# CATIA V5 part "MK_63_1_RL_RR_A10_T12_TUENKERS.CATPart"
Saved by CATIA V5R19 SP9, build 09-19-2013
Part number: MK_63_1_RL_RR_A10_T12_TUENKERS
Material "MISCHDICHTE": density 5043 kg/m3, Young's modulus 2e+11 Pa, Poisson ratio 0.266
Bounding box of the stored display mesh (mm): x -193.5 to 132.266, y -121.5 to 144, z -122.161 to 122.161
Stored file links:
  G:\Konstruktion\Modelle\Catia_V5\MK_63_1_RL_RR_A10_T12_TUENKERS.CATPart
  G:\Konstruktion\Modelle\Catia_V5\Spannarme\SPANNARM_KPL_63_A10_217498_TUENKERS.CATPart
  C:\Catia\Tuenkers_B19SP9HF86_64\win_b64\reffiles\standard\MetricThickPitch.txt
  G:\Konstruktion\Modelle\Catia_V5\MK_63_1_A10_T00_TUENKERS.CATPart
  G:\Konstruktion\Modelle\Catia_V5\MK2_63_1_A40_T12_TUENKERS.CATPart
  G:\Konstruktion\Modelle\Catia_V5\V2_63_1_BR3_ZL_ZR_RL_RR_A40_T12_TUENKERS.CATPart
  HANDHEBEL_KPL_50_63_TUENKERS.CATPart
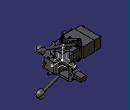
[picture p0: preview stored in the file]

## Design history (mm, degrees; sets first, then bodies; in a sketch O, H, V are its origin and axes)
AxisSystem1: origin (0, 0, 0), X (1, 0, 0), Y (0, 1, 0), Z (0, 0, 1)
Body1 (main body)
  Body2 "*DIT1\\*DIT2\\"
    Solid1: solid without history
  Assemble1: tool Body2
  Body3 "*DIT1\\*DIT3"
    Solid2 "Solid.1": solid without history
  Assemble2: tool Body3
  Body4 "*DIT1\\*DIT12\\*DIT16\\"
    Solid3 "Solid.1": solid without history
  Assemble3: tool Body4
  Body5 "*DIT1\\*DIT12\\*DIT17\\"
    Solid4 "Solid.1": solid without history
  Assemble4: tool Body5
  Body6 "*DIT1\\*DIT12\\MK_MK2_63_1_A10_A11_A12_T12_081112_3D_xSET4_2.1"
    Solid5 "Solid.1": solid without history
    Body7 "*DIT1\\*DIT12\\MK_MK2_63_1_A10_A11_A12_T12_081112_3D_xSET4_2.1\\Body.11 ( *SOL16 - wsp GEHAEUSE -  )"
      Solid6 "Solid.1": solid without history
    Add1 "*DIT1\\*DIT12\\MK_MK2_63_1_A10_A11_A12_T12_081112_3D_xSET4_2.1\\Body.11 ( *SOL16 - wsp GEHAEUSE -  )": tool Body7
    Body8 "*DIT1\\*DIT12\\MK_MK2_63_1_A10_A11_A12_T12_081112_3D_xSET4_2.1\\Body.12 ( *SOL17 - wsp GEHAEUSE -  )"
      Solid7 "Solid.1": solid without history
    Add2 "*DIT1\\*DIT12\\MK_MK2_63_1_A10_A11_A12_T12_081112_3D_xSET4_2.1\\Body.12 ( *SOL17 - wsp GEHAEUSE -  )": tool Body8
    Body9 "*DIT1\\*DIT12\\MK_MK2_63_1_A10_A11_A12_T12_081112_3D_xSET4_2.1\\Body.14 ( *SOL18 - wsp GEHAEUSE -  )"
      Solid8 "Solid.1": solid without history
    Add3 "*DIT1\\*DIT12\\MK_MK2_63_1_A10_A11_A12_T12_081112_3D_xSET4_2.1\\Body.14 ( *SOL18 - wsp GEHAEUSE -  )": tool Body9
  Assemble5: tool Body6
  Body10 "*DIT1\\MK_MK2_63_1_A10_A11_A12_T12_081112_3D_xSET2_1.1"
    Solid9 "Solid.1": solid without history
  Assemble6: tool Body10
  Rotate1: Axis edge [XY plane of AxisSystem1 | ZX plane of AxisSystem1], Angle 90, ToTransfor Assemble6
  Body11
    Body12 "*DIT1\\MK_MK2_63_1_A10_A11_A12_T12_081112_3D_xSET2_1.1\\Body.2 ( *SOL2 - wsp MK_MK2 63_1 -  )"
      Solid10 "Solid.1": solid without history
    Assemble7: tool Body12
    Body13 "*DIT1\\MK_MK2_63_1_A10_A11_A12_T12_081112_3D_xSET2_1.1\\Body.3 ( *SOL3 - wsp MK_MK2 63_1 -  )"
      Solid11 "Solid.1": solid without history
    Assemble8: tool Body13
    Body14 "*DIT1\\MK_MK2_63_1_A10_A11_A12_T12_081112_3D_xSET2_1.1\\Body.4 ( *SOL4 - wsp MK_MK2 63_1 -  )"
      Solid12 "Solid.1": solid without history
    Assemble9: tool Body14
    Body15 "*DIT1\\MK_MK2_63_1_A10_A11_A12_T12_081112_3D_xSET2_1.1\\Body.5 ( *SOL5 - wsp MK_MK2 63_1 -  )"
      Solid13 "Solid.1": solid without history
    Assemble10: tool Body15
    Body16 "*DIT1\\MK_MK2_63_1_A10_A11_A12_T12_081112_3D_xSET2_1.1\\Body.6 ( *SOL6 - wsp MK_MK2 63_1 -  )"
      Solid14 "Solid.1": solid without history
    Assemble11: tool Body16
    Rotate2: Axis edge, Angle 90, ToTransfor Assemble11
    Translate1: Direction edge [YZ plane of AxisSystem1 | XY plane of AxisSystem1], Length -1, ToTransfor Rotate2
  Assemble12: tool Body11
Body17 "Spannarm_kpl_63_A10_217498_Tuenkers", material "Steel"
  Sketch1 on xy-plane, origin (0, 0, 0), H (1, 0, 0), V (0, 1, 0)
    line L1 (43, 144) -> (15, 144)
    arc A1 centre (21.5, 11.6005) radius 20 from (35.6421, -2.5416) to (41.5, 11.6005) ccw
    line L2 (35.6421, -2.5416) -> (19.0919, -19.0919)
    line L3 (10.9602, 10.9602) -> (10.9602, -10.9602)
    line L4 (10.9602, 10.9602) -> (-10.9602, 10.9602)
    line L5 (-19.0919, 19.0919) -> (-10.9602, 10.9602)
    line L6 (10.6421, 48.8259) -> (-19.0919, 19.0919)
    line L7 (16.5, 62.968) -> (16.5, 78.0635)
    line L8 (43, 144) -> (43, 80)
    line L9 (10.9602, -10.9602) -> (19.0919, -19.0919)
    point P7 (10.9602, 10.9602)
    point P10 (-1.4396, 36.7442)
    point P11 (73, 37.6447)
    point P12 (45, 51.7188)
    reference intersected line E1 through (0, 0) direction (-0.7071, 0.7071)
    reference intersected line E2 through (0, 0) direction (-0.7071, 0.7071)
    reference intersected line E3 through (0, 0) direction (-0.7071, 0.7071)
    reference intersected line E4 through (0, 0) direction (0, 1) from yz-plane
    reference intersected line E5 through (0, 0) direction (-1, 0) from zx-plane
    line L10 (41.5, 78.0635) -> (41.5, 11.6005)
    line L11 (15, 80) -> (15, 144)
    arc A2 centre (-3.5, 62.968) radius 20 from (10.6421, 48.8259) to (16.5, 62.968) ccw
    arc A3 centre (14.5, 78.0635) radius 2 from (16.5, 78.0635) to (15, 80) ccw
    arc A4 centre (43.5, 78.0635) radius 2 from (41.5, 78.0635) to (43, 80) cw
    reference intersected line E6 through (0, 0) direction (0, 1) from yz-plane
    radius A1 = 20
    angle L4 L5 = 45
    distance P7 L2 = 27
    distance L2 L6 = 54
    angle L2 L9 = 90
    distance P7 E1 = 15.5
    distance E4 L3 = 10.9602
    distance E5 L1 = 144
    distance P10 L1 = 107.2558
    radius A4 = 2
    radius A3 = 2
    distance L10 L8 = 1.5
    distance L7 L10 = 25
    distance E6 L11 = 15
    distance L11 L7 = 1.5
    length L8 = 64
    radius A2 = 20
    length L11 = 64
    tangency: A1 L2, A1 L10, A4 L10, A2 L7, L6 A2, A3 L7
    coincidence: L9 E2, L5 E3, L6 P10
  Pad1: profile Sketch1, direction (0, 0, 1), length 39, opposite side length 39
  Chamfer1: length 0.1, angle 45, on edge [face of Pad1 from Sketch1.L3 | end face of Pad1]; edge [face of Pad1 from Sketch1.L4 | end face of Pad1]; edge [start face of Pad1 | face of Pad1 from Sketch1.L4]; edge [start face of Pad1 | face of Pad1 from Sketch1.L3]
  Sketch2 on face of Pad1 from Sketch1.L8, origin (43, 0, 0), H (0, 1, 0), V (0, 0, 1)
    line L1 (144, -10) -> (144, 10)
    line L2 (103, 10) -> (144, 10)
    arc A1 centre (103, 18) radius 8 from (103, 10) to (95, 18) cw
    line L3 (95, 24.9808) -> (95, 18)
    line L4 (-20, 39) -> (70, 39)
    line L5 (-20, 39) -> (-20, 28)
    line L6 (74, 28) -> (-20, 28)
    arc A2 centre (74, 22) radius 6 from (74, 28) to (80, 22) cw
    line L7 (80, 22) -> (80, -22)
    arc A3 centre (74, -22) radius 6 from (80, -22) to (74, -28) cw
    line L8 (-20, -28) -> (74, -28)
    line L9 (-20, -28) -> (-20, -39)
    line L10 (-20, -39) -> (70, -39)
    line L11 (95, -24.9808) -> (95, -18)
    arc A4 centre (103, -18) radius 8 from (95, -18) to (103, -10) cw
    line L12 (103, -10) -> (144, -10)
    reference intersected line E1 through (0, 0) direction (-1, 0) from xy-plane
    reference intersected line E2 through (0, 0) direction (0, 1) from zx-plane
    reference intersected line E3 through (0, 0) direction (0, 1) from zx-plane
    reference intersected line E4 through (0, 0) direction (0, 1) from zx-plane
    line L13 (-30, -44) -> (160, -44)
    line L14 (160, -44) -> (160, 44)
    line L15 (160, 44) -> (-30, 44)
    line L16 (-30, 44) -> (-30, -44)
    reference intersected line E5 through (0, 0) direction (-1, 0) from xy-plane
    reference intersected line E6 through (0, 0) direction (0, 1) from zx-plane
    line L17 (72.5882, -38.6593) -> (87.5882, -34.64)
    line L18 (87.5882, 34.64) -> (72.5882, 38.6593)
    arc A5 centre (85, 24.9808) radius 10 from (95, 24.9808) to (87.5882, 34.64) ccw
    arc A6 centre (70, 29) radius 10 from (72.5882, 38.6593) to (70, 39) ccw
    point P23 (70, 39)
    arc A7 centre (70, -29) radius 10 from (72.5882, -38.6593) to (70, -39) cw
    point P26 (70, -39)
    arc A8 centre (85, -24.9808) radius 10 from (95, -24.9808) to (87.5882, -34.64) cw
    distance L12 E1 = 10
    distance L12 L2 = 20
    distance L4 L10 = 78
    distance L6 L8 = 56
    distance L10 L12 = 29
    distance L8 L10 = 11
    radius A2 = 6
    radius A3 = 6
    radius A1 = 8
    radius A4 = 8
    distance L7 E2 = 80
    distance L3 E3 = 95
    distance L1 L5 = 164
    distance E4 L1 = 144
    distance L16 L14 = 190
    distance L15 L13 = 88
    distance L13 E5 = 44
    distance L14 E6 = 160
    angle L18 L4 = 15
    distance P23 L3 = 25
    radius A6 = 10
    radius A5 = 10
    angle L10 L17 = 15
    distance L11 P26 = 25
    radius A7 = 10
    radius A8 = 10
    tangency: L6 A2, A2 L7, L7 A3, A3 L8, L3 A1, A1 L2, A4 L12, A4 L11, A5 L3, A5 L18, A6 L18, A6 L4, A7 L17, A7 L10, A8 L11, A8 L17
    vertical: L1 V, L14 V, L16 V
    horizontal: L12 H, L13 H, L15 H
    coincidence: L5 L9, L11 L3
  Pocket1: profile Sketch2, direction (-1, 0, 0), length 95
  Sketch3 on face of Pad1 from Sketch1.L8, origin (43, 131.0889, -0.3784), H (0, 1, 0), V (0, 0, 1)
    point P1 (3.9111, 0.3784)
    reference intersected line E1 through (0, 0.3784) direction (-1, 0) from xy-plane
    reference intersected line E2 through (-131.0889, 0) direction (0, 1) from zx-plane
    reference intersected line E3 through (-131.0889, 0) direction (0, 1) from zx-plane
    reference intersected line E4 (12.9111, -38.6216) -> (-51.0889, -38.6216) from start face of Pad1
    distance P1 E2 = 135
    distance E3 E4 = 0
    coincidence: P1 E1
  Hole1: placed by Sketch3, at (43, 135, 0) direction (-1, 0, 0), diameter 6, through (limit type 6)
  Sketch4 on face of Pad1 from Sketch1.L8, origin (43, 113.9529, 0.5693), H (0, 1, 0), V (0, 0, 1)
    point P1 (-8.9529, -0.5693)
    reference projected point E1 (21.0471, -0.5693) from axis of face of Hole1
    reference intersected line E2 through (0, -0.5693) direction (-1, 0) from xy-plane
    distance P1 E1 = 30
    coincidence: P1 E2
  Hole2: placed by Sketch4, at (43, 105, 0) direction (-1, 0, 0), diameter 6, through (limit type 6)
  Sketch5 on face of Pad1 from Sketch1.L8, origin (43, 123.4122, -0.1089), H (0, 1, 0), V (0, 0, 1)
    point P1 (-3.4122, 0.1089)
    reference projected point E1 (11.5878, 0.1089) from axis of face of Hole1
    reference projected point E2 (-18.4122, 0.1089) from axis of face of Hole2
    distance P1 E1 = 15
    distance E2 P1 = 15
  Hole3: placed by Sketch5, at (43, 120, 0) direction (-1, 0, 0), diameter 9, through (limit type 6)
  Sketch6 on face of Pad1 from Sketch1.L8, origin (43, 93.5248, 1.4062), H (0, 1, 0), V (0, 0, 1)
    point P1 (-3.5248, -1.4062)
    reference projected point E1 (26.4752, -1.4062) from axis of face of Hole3
    reference projected point E2 (11.4752, -1.4062) from axis of face of Hole2
    distance P1 E1 = 30
    distance P1 E2 = 15
  Hole4: placed by Sketch6, at (43, 90, 0) direction (-1, 0, 0), diameter 9, through (limit type 6)
  Sketch7 on face of Pad1 from Sketch1.L9, origin (13.7879, -13.7879, 28.7565), H (0.7071, -0.7071, 0), V (0, 0, 1)
    point P1 (0.5009, 4.2435)
    reference intersected line E1 through (0, -28.7565) direction (-1, 0) from xy-plane
    reference projected line E2 (-19.4991, -67.7565) -> (-19.4991, 10.2435) from edge [face of Pad1 from Sketch1.L3 | face of Pad1 from Sketch1.L4]
    distance P1 E1 = 33
    distance E2 P1 = 20
  Hole5: placed by Sketch7, at (14.1421, -14.1421, 33) direction (0.7071, 0.7071, 0), diameter 6.647, depth 18, V-bottom angle 120, threaded "M8", thread diameter 8, thread depth 15, pitch 1.25
  RectPattern1: of Hole5, direction 1 instances 2, spacing 66, along edge [face of Pad1 from Sketch1.L3 | face of Pad1 from Sketch1.L4] reversed, direction 2 instances 2, spacing 40, along edge [face of Pad1 from Sketch1.L9 | face of Pocket1] reversed
  Sketch8 on face of Pocket1 from Sketch2.L6, origin (0, 0, 28), H (1, 0, 0), V (0, -1, 0)
    line L1 (19.0919, 19.0919) -> (35.6421, 2.5416)
    line L2 (36.7245, 1.3692) -> (-1.4142, -36.7696)
    line L3 (-1.4142, -36.7696) -> (-19.0919, -19.0919)
    line L4 (-19.0919, -19.0919) -> (-10.96, -10.96)
    line L5 (-10.96, -10.96) -> (10.96, -10.96)
    point P5 (10.96, -10.96)
    line L6 (10.96, -10.96) -> (10.96, 10.96)
    line L7 (10.96, 10.96) -> (19.0919, 19.0919)
    reference intersected line E1 through (0, 0) direction (0.7071, -0.7071)
    reference intersected line E2 through (0, 0) direction (0.7071, 0.7071)
    reference intersected line E3 through (0, 0) direction (0.7071, -0.7071)
    arc A1 centre (21.5, -11.6005) radius 20 from (35.6421, 2.5416) to (36.7245, 1.3692) cw
    reference intersected line E4 through (0, 0) direction (0, 1) from yz-plane
    distance E1 L1 = 27
    distance L3 L1 = 54
    distance L7 L2 = 25
    angle L6 L5 = 90
    radius A1 = 20
    length L2 = 53.9363
    distance E4 L6 = 10.96
    coincidence: E2 L7, L4 L7, P5 E3
    tangency: A1 L1
  Pad2: profile Sketch8, direction (0, 0, -1), length 1
  Mirror1: of Pad2, Sketch8, about xy-plane
  Body18 "KLEMMFLANSCH KPL"
    Sketch9 on xy-plane, origin (0, 0, 0), H (1, 0, 0), V (0, 1, 0)
      line L1 (-20.5061, 17.6777) -> (-31.1375, 7.0463)
      line L2 (-31.1375, 7.0463) -> (-19.1167, -4.9745)
      line L3 (-19.1167, -4.9745) -> (-25.4806, -11.3385)
      line L4 (-25.4806, -11.3385) -> (-11.3385, -25.4806)
      line L5 (-11.3385, -25.4806) -> (-4.9745, -19.1167)
      line L6 (-4.9745, -19.1167) -> (7.0463, -31.1375)
      line L7 (7.0463, -31.1375) -> (19.0671, -19.1167)
      line L8 (19.0671, -19.1167) -> (10.9106, -10.9602)
      line L9 (10.9106, -10.9602) -> (-10.9602, -10.9602)
      point P10 (-10.9602, -10.9602)
      line L10 (-10.9602, -10.9602) -> (-10.9602, 8.1317)
      line L11 (-10.9602, 8.1317) -> (-20.5061, 17.6777)
      reference intersected line E1 through (0, 0) direction (-0.7071, 0.7071)
      reference intersected line E2 through (0, 0) direction (-0.7071, 0.7071)
      reference intersected line E3 through (0, 0) direction (-0.7071, -0.7071)
      distance L4 L8 = 26
      distance L7 L5 = 17
      distance L5 L3 = 20
      distance L7 L1 = 54
      distance L4 L6 = 9
      distance E1 P10 = 15.5
      distance L11 E2 = 2
      distance L11 L8 = 1.965
      angle L11 L10 = 135
      angle L9 L8 = 45
      distance L7 P10 = 27
      distance E3 L7 = 27
      coincidence: L2 L6
    Pad3: profile Sketch9, direction (0, 0, 1), length 39, opposite side length -27
    Chamfer2: length 0.1, angle 45, on edge [face of Pad3 from Sketch9.L9 | end face of Pad3]; edge [face of Pad3 from Sketch9.L10 | end face of Pad3]
    Sketch10 on face of Pad3 from Sketch9.L6, origin (-12.0456, -12.0456, 0), H (0.7071, -0.7071, 0), V (0, 0, 1)
      circle A1 centre (20, 33) radius 4
      point P1 (20, 33)
      circle A2 centre (-20, 33) radius 4
      point P2 (-20, 33)
      reference projected line E1 (-27, 27) -> (-10, 27) from edge [start face of Pad3 | face of Pad3 from Sketch9.L2]
      reference projected line E2 (10, 27) -> (27, 27) from edge [start face of Pad3 | face of Pad3 from Sketch9.L6]
      reference projected line E3 (27, 27) -> (27, 39) from edge [face of Pad3 from Sketch9.L7 | face of Pad3 from Sketch9.L6]
      reference projected line E4 (-27, 27) -> (-27, 39) from edge [face of Pad3 from Sketch9.L2 | face of Pad3 from Sketch9.L1]
      radius A1 = 4
      radius A2 = 4
      distance E1 P2 = 6
      distance P1 E2 = 6
      distance E3 P1 = 7
      distance P2 E4 = 7
    Pad4: profile Sketch10, direction (0.7071, 0.7071, 0), length 20
    Sketch11 on face of Pad4, origin (-12.0456, -12.0456, 0), H (0.7071, -0.7071, 0), V (0, 0, 1)
      circle A1 centre (20, 33) radius 6.5
      point P1 (20, 33)
      circle A2 centre (-20, 33) radius 6.5
      point P2 (-20, 33)
      reference projected line E1 (-27, 27) -> (-27, 39) from edge [face of Pad3 from Sketch9.L2 | face of Pad3 from Sketch9.L1]
      reference projected line E2 (27, 27) -> (27, 39) from edge [face of Pad3 from Sketch9.L7 | face of Pad3 from Sketch9.L6]
      reference projected line E3 (-27, 27) -> (-10, 27) from edge [start face of Pad3 | face of Pad3 from Sketch9.L2]
      reference projected line E4 (10, 27) -> (27, 27) from edge [start face of Pad3 | face of Pad3 from Sketch9.L6]
      radius A1 = 6.5
      radius A2 = 6.5
      distance E1 P2 = 7
      distance E2 P1 = 7
      distance E3 P2 = 6
      distance E4 P1 = 6
    Pad5: profile Sketch11, direction (-0.7071, -0.7071, 0), length 1.4
    Chamfer3: length 0.1, angle 45, on edge [face of Pad5 from Sketch11.A1 | end face of Pad5]; edge [face of Pad5 from Sketch11.A2 | end face of Pad5]
    Sketch12 on end face of Pad5, origin (-13.0355, -13.0355, 0), H (0.7071, -0.7071, 0), V (0, 0, 1)
      circle A1 centre (20, 33) radius 6.5
      point P1 (20, 33)
      circle A2 centre (-20, 33) radius 6.5
      point P2 (-20, 33)
      reference projected line E1 (10, 27) -> (27, 27) from edge [start face of Pad3 | face of Pad4]
      reference projected line E2 (27, 27) -> (27, 39) from edge [face of Pad3 from Sketch9.L7 | face of Pad3 from Sketch9.L6]
      reference projected line E3 (-27, 27) -> (-27, 39) from edge [face of Pad3 from Sketch9.L2 | face of Pad3 from Sketch9.L1]
      reference projected line E4 (-27, 27) -> (-10, 27) from edge [start face of Pad3 | face of Pad4]
      radius A1 = 6.5
      radius A2 = 6.5
      distance E1 P1 = 6
      distance E2 P1 = 7
      distance E3 P2 = 7
      distance E4 P2 = 6
    Pad6: profile Sketch12, direction (-0.7071, -0.7071, 0), length 8
    Fillet1: radius 0.5, on end face of Pad6; edge [face of Pad6 from Sketch12.A1 | end face of Pad6]
    Mirror2: of the body so far, about xy-plane, deactivated
  Assemble13: tool Body18
Body19 "ENDLAGENRASTE_LINKS"
  Solid15 "Manifold Solid #1213": solid without history
  Body20 "LUMP70"
    Solid16 "Manifold Solid #2778": solid without history
  Assemble14: tool Body20
  Body21 "LUMP73"
    Solid17 "Manifold Solid #4455": solid without history
  Assemble15: tool Body21
  Body22 "LUMP74"
    Solid18 "Manifold Solid #5598": solid without history
  Assemble16: tool Body22
  Body23 "LUMP76"
    Solid19 "Manifold Solid #7126": solid without history
  Assemble17: tool Body23
  Body24 "LUMP79"
    Solid20 "Manifold Solid #8329": solid without history
  Assemble18: tool Body24
  Body25 "LUMP81"
    Solid21 "Manifold Solid #8843": solid without history
  Assemble19: tool Body25
  Body26 "LUMP82"
    Solid22 "Manifold Solid #9252": solid without history
  Assemble20: tool Body26
  Body27 "LUMP85"
    Solid23 "Manifold Solid #10175": solid without history
  Assemble21: tool Body27
  Body28 "LUMP87"
    Solid24 "Manifold Solid #10993": solid without history
  Assemble22: tool Body28
  Body29 "LUMP88"
    Solid25 "Manifold Solid #11378": solid without history
  Assemble23: tool Body29
  Body30 "LUMP89"
    Solid26 "Manifold Solid #12146": solid without history
  Assemble24: tool Body30, deactivated
  Body31 "LUMP93"
    Solid27 "Manifold Solid #13965": solid without history
  Assemble25: tool Body31, deactivated
  Body32 "LUMP94"
    Solid28 "Manifold Solid #14222": solid without history
  Assemble26: tool Body32, deactivated
  Body33 "LUMP97"
    Solid29 "Manifold Solid #15145": solid without history
  Assemble27: tool Body33, deactivated
  Body34 "LUMP98"
    Solid30 "Manifold Solid #15554": solid without history
  Assemble28: tool Body34, deactivated
  Body35 "LUMP101"
    Solid31 "Manifold Solid #16781": solid without history
  Assemble29: tool Body35
  Body36 "LUMP102"
    Solid32 "Manifold Solid #17038": solid without history
  Assemble30: tool Body36
  Rotate3: Axis edge, Angle 90, ToTransfor Assemble30
Body37 "ENDLAGENRASTE_RECHTS"
  Body38 "LUMP69"
    Solid33 "Manifold Solid #2521": solid without history
  Assemble31: tool Body38
  Body39 "LUMP71"
    Solid34 "Manifold Solid #3035": solid without history
  Assemble32: tool Body39
  Body40 "LUMP72"
    Solid35 "Manifold Solid #3745": solid without history
  Assemble33: tool Body40
  Body41 "LUMP75"
    Solid36 "Manifold Solid #6741": solid without history
  Assemble34: tool Body41
  Body42 "LUMP77"
    Solid37 "Manifold Solid #7511": solid without history
  Assemble35: tool Body42
  Body43 "LUMP78"
    Solid38 "Manifold Solid #7920": solid without history
  Assemble36: tool Body43
  Body44 "LUMP80"
    Solid39 "Manifold Solid #8586": solid without history
  Assemble37: tool Body44
  Body45 "LUMP83"
    Solid40 "Manifold Solid #9661": solid without history
  Assemble38: tool Body45
  Body46 "LUMP84"
    Solid41 "Manifold Solid #9918": solid without history
  Assemble39: tool Body46
  Body47 "LUMP86"
    Solid42 "Manifold Solid #10584": solid without history
  Assemble40: tool Body47
  Body48 "LUMP90"
    Solid43 "Manifold Solid #12531": solid without history
  Assemble41: tool Body48
  Body49 "LUMP91"
    Solid44 "Manifold Solid #13299": solid without history
  Assemble42: tool Body49
  Body50 "LUMP92"
    Solid45 "Manifold Solid #13708": solid without history
  Assemble43: tool Body50
  Body51 "LUMP95"
    Solid46 "Manifold Solid #14479": solid without history
    Translate2: Direction edge [face of Solid44 | face of Solid44], Length -4, ToTransfor Solid46
  Assemble44: tool Body51
  Body52 "LUMP96"
    Solid47 "Manifold Solid #14736": solid without history
    Translate3: Direction edge [face of Solid44 | face of Solid44], Length -4, ToTransfor Solid47
  Assemble45: tool Body52
  Body53 "LUMP99"
    Solid48 "Manifold Solid #15963": solid without history
    Translate4: Direction edge [face of Solid44 | face of Solid44], Length -4, ToTransfor Solid48
  Assemble46: tool Body53
  Body54 "LUMP100"
    Solid49 "Manifold Solid #16372": solid without history
    Translate5: Direction edge [face of Solid44 | face of Solid44], Length -4, ToTransfor Solid49
  Assemble47: tool Body54
  Body55 "LUMP103"
    Solid50 "Manifold Solid #17295": solid without history
  Assemble48: tool Body55
  Rotate4: Axis edge, Angle 90, ToTransfor Assemble48
Body56 "Handhebel_KPL_218625_TUENKERS.1"
  Solid51: solid without history
  Body57 "Handhebel_KPL_218625_TUENKERS.2"
    Solid52: solid without history
  Assemble49: tool Body57
  Translate6: ToTransfor Assemble49, Direction edge [ZX plane of AxisSystem1 | YZ plane of AxisSystem1], Length 28
  Translate7: ToTransfor Translate6, Direction edge [XY plane of AxisSystem1 | ZX plane of AxisSystem1], Length -86
  Translate8: ToTransfor Translate7, Direction edge [YZ plane of AxisSystem1 | XY plane of AxisSystem1], Length -4
Body58 "Handhebel_KPL_218625_TUENKERS.1"
  Solid53: solid without history
  Body59 "Handhebel_KPL_218625_TUENKERS.2"
    Solid54: solid without history
  Assemble50: tool Body59
  Translate9: Direction edge [ZX plane of AxisSystem1 | YZ plane of AxisSystem1], Length 28, ToTransfor Assemble50
  Translate10: Direction edge [XY plane of AxisSystem1 | ZX plane of AxisSystem1], Length -86, ToTransfor Translate9
  Translate11: Direction edge [YZ plane of AxisSystem1 | XY plane of AxisSystem1], Length -4, ToTransfor Translate10
  Symmetry1: ToTransfor Translate11, Reference XY plane of AxisSystem1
